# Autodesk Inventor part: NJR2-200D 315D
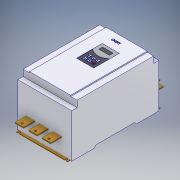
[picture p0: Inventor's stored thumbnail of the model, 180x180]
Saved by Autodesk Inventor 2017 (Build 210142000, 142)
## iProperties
Part Number: NJR2-200D 315D
Material: Типовые
Document SubType Name: Modeling
Designer: RSagdiev
Density: 1 g/cm^3
Appearance: По умолчанию
Author: RSagdiev
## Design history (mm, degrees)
sketch "Эскиз1"
  geometry: L1 (0, 0)-(15.898, 0) reference; L2 (0, 0)-(0, 16.101) reference; L3 (0, 0)-(105, 0); L4 (410, 0)-(410, 206); L5 (410, 241)-(0, 241); L6 (0, 241)-(0, 206); L7 (115, -10)-(295, -10); L8 (295, -10)-(295, 0); L9 (295, 10)-(115, 10); L10 (115, 10)-(115, 10); L11 (115, -10)-(295, 10); L12 (295, -10)-(115, 10); L13 (305, 0)-(410, 0); L14 (115, 0)-(205, 0); L15 (205, 0)-(295, 0); L16 (295, 10)-(295, 10); L17 (115, 0)-(115, -10); L18 (295, 10)-(305, 0); L19 (115, 10)-(105, 0); L20 (410, 241)-(385, 241); L21 (385, 241)-(385, 206); L22 (385, 206)-(410, 206); L23 (410, 206)-(410, 241); L24 (0, 241)-(25, 241); L25 (25, 241)-(25, 206); L26 (25, 206)-(0, 206); L27 (0, 206)-(0, 241); L28 (410, 206)-(410, 241); L29 (0, 206)-(0, 0); 1 further point
  constraints: 58 end point, 17 parallel, 12 perpendicular, 9 horizontal, 4 midpoint, 4 point on line, 2 vertical, 1 other
  dimensions: "d0" = 410 distance of L5.end L5.start; "d1" = 241 distance of L5.start L4.start; "d2" = 180 distance of L9.end L9.start; "d3" = 20 distance of L9.start L7.end; "d4" = 205 distance from line of L14.end L4 (= 0.5 x d0); "d5" = 10 distance of L16.start L8.end; "d6" = 10 distance of L13.start L8.end (= d5); "d7" = 10 distance of L10.end L14.start (= d5); "d8" = 10 distance of L3.end L14.start (= d7); "d9" = 25 distance of L4.end L21.end; "d10" = 35 distance of L21.end L20.end; "d11" = 25 distance of L25.end L6.end; "d12" = 35 distance of L24.end L25.end
extrude "Выдавливание1" new body sketch "Эскиз1" stored distance "d13" = 253; taper "d14" = 0 deg
sketch "Эскиз2"
  geometry: L1 (0, 0)-(253, 0) reference; L2 (253, 360)-(253, 0) reference; L3 (253, 360)-(0, 360) reference; L4 (0, 0)-(0, 360) reference; L5 (0, 0)-(0, 360) reference; L6 (0, 0)-(253, 0) reference; L7 (0, 360)-(30, 360); L8 (30, 360)-(30, 0); L9 (30, 0)-(0, 0); L10 (0, 0)-(0, 360); L11 (253, 360)-(223, 360); L12 (223, 360)-(223, 0); L13 (223, 0)-(253, 0); L14 (253, 0)-(253, 360); 1 further point
  constraints: 16 end point, 4 parallel, 2 horizontal, 2 perpendicular, 2 point on line
  dimensions: "d15" = 30 distance of L8.end L9.end; "d16" = 30 distance of L13.end L12.end
extrude "Выдавливание2" cut sketch "Эскиз2" distance "d17" = 5; taper "d18" = 0 deg
sketch "Эскиз3"
  geometry: L1 (385, 236)-(25, 236) reference; L2 (25, 236)-(25, 206) reference; L3 (25, 206)-(0, 206) reference; L4 (0, 206)-(0, 0) reference; L5 (0, 0)-(105, 0) reference; L6 (105, 0)-(115, 10) reference; L7 (115, 10)-(295, 10) reference; L8 (295, 10)-(305, 0) reference; L9 (305, 0)-(410, 0) reference; L10 (410, 0)-(410, 206) reference; L11 (410, 206)-(385, 206) reference; L12 (385, 206)-(385, 236) reference; L13 (423, 3.5)-(315, 3.5); L14 (315, 3.5)-(315, 0.5); L15 (315, 0.5)-(423, 0.5); L16 (423, 0.5)-(423, 3.5); L17 (115, 10)-(295, 10) reference; L18 (205, 10)-(205, 236); L19 (115, 10)-(105, 0); L20 (95, 3.5)-(95, 0.5); L21 (105, 0)-(0, 0); L22 (-13, 3.5)-(95, 3.5); L23 (-13, 0.5)-(-13, 3.5); L24 (95, 0.5)-(-13, 0.5); 1 further point
  constraints: 22 end point, 4 symmetric about line, 2 midpoint, 2 parallel, 1 horizontal, 1 perpendicular
  dimensions: "d20" = 3 distance of L14.end L13.end; "d21" = 0.5 distance between parallel lines of L9 L15; "d23" = 10 distance from line of L8.end L14; "d24" = 436 distance between parallel lines of L23 L16
extrude "Выдавливание3" new body sketch "Эскиз3" stored distance "d25" = 240; taper "d26" = 0 deg
sketch "Эскиз4"
  geometry: L1 (240, 0)-(0, 0) reference; L2 (0, -108)-(0, 0) reference; L3 (240, -108)-(0, -108) reference; L4 (240, 0)-(240, -108) reference; L5 (240, 0)-(0, 0) reference; L6 (120, 0)-(120, -108); L7 (240, -108)-(0, -108) reference; L8 (240, -328)-(0, -328) reference; L9 (0, -436)-(0, -328) reference; L10 (240, -436)-(0, -436) reference; L11 (240, -328)-(240, -436) reference; L12 (10, -429.5)-(10, -436); L13 (6.5, -429.5)-(6.5, -436); L14 (13.5, -436)-(13.5, -429.5); L15 (230, -429.5)-(230, -436); L16 (226.5, -429.5)-(226.5, -436); L17 (233.5, -436)-(233.5, -429.5); C1 r 3.5 at (10, -6.5); C2 r 3.5 at (230, -6.5); A1 r 3.5 centre (10, -429.5) between (13.5, -429.5) and (6.5, -429.5); A2 r 3.5 centre (10, -436) between (6.5, -436) and (13.5, -436); A3 r 3.5 centre (230, -429.5) between (233.5, -429.5) and (226.5, -429.5); A4 r 3.5 centre (230, -436) between (226.5, -436) and (233.5, -436); 3 further points
  constraints: 18 end point, 8 point on circle, 8 tangent, 6 centre point, 4 midpoint, 2 parallel, 2 perpendicular, 2 point on line
  dimensions: "d27" = 7 diameter of C1; "d28" = 7 diameter of C2 (= d27); "d29" = 220 distance of C2.centre C1.centre; "d31" = 110 distance from line of C1.centre L6 (= 0.5 x d29); "d32" = 110 distance from line of L6 C2.centre (= d31); "d33" = 6.5 distance from line of L1 C1.centre (computed from d27); "d34" = 6.5 distance from line of L1 C2.centre (derived); "d35" = 7 diameter of A2 (= d27); "d36" = 6.5 distance from line of L10 L12.start (computed from d35); "d37" = 7 diameter of A4 (= d35); "d38" = 6.5 distance from line of L10 L15.start (= d36); "d39" = 220 distance of L15.start L12.start (= d29); "d40" = 110 horizontal distance of point (120, -423) L12.start (= d31); "d41" = 110 horizontal distance of point (120, -423) L15.start (derived)
extrude "Выдавливание4" cut sketch "Эскиз4" stored distance "d42" = 240; taper "d43" = 0 deg
node "РабПлоскость1"
sketch "Эскиз5" dims "d56" = 10, "d67" = 10
  geometry: L1 (33.5, 147)-(73.5, 147); L2 (73.5, 147)-(73.5, -367); L3 (73.5, -367)-(33.5, -367); L4 (33.5, -367)-(33.5, 147); L5 (-6.5, 95)-(246.5, 95) reference; L6 (-6.5, -20)-(-6.5, -200) reference; L7 (-6.5, -110)-(246.5, -110); L8 (246.5, -200)-(246.5, -20) reference; L9 (96.75, 147)-(136.75, 147); L10 (136.75, 147)-(136.75, -367); L11 (136.75, -367)-(96.75, -367); L12 (96.75, -367)-(96.75, 147); L13 (160, 147)-(200, 147); L14 (200, 147)-(200, -367); L15 (200, -367)-(160, -367); L16 (160, -367)-(160, 147); C1 r 5 at (53.5, 135); C2 r 5 at (116.75, 135); C3 r 5 at (180, 135); C4 r 5 at (116.75, -355); C5 r 5 at (180, -355); C6 r 5 at (53.5, -355); 1 further point
  constraints: 26 end point, 6 centre point, 3 horizontal, 3 symmetric about line, 2 midpoint, 2 parallel, 1 perpendicular, 23 other
  dimensions: "d45" = 514 distance between parallel lines of L3 L1; "d46" = 40 distance between parallel lines of L2 L4; "d48" = 257 distance between parallel lines of L1 L7 (= 0.5 x d45); "d49" = 40 distance between parallel lines of L4 L6; "d50" = 253 distance between parallel lines of L8 L6 (derived); "d53" = 63.25 distance of L1.start L9.start (= 0.25 x d50); "d59" = 10 diameter of C1; "d60" = 20 distance from line of C1.centre L4; "d61" = 12 distance from line of C1.centre L1; "d64" = 63.25 distance of C1.centre C2.centre (= d53)
extrude "Выдавливание5" new body sketch "Эскиз5" distance "d69" = 5; taper "d70" = 0 deg
node "РабПлоскость2"
sketch "Эскиз6" dims "d79" = 10, "d89" = 10
  geometry: L1 (73.5, 147)-(33.5, 147) reference; L2 (33.5, 147)-(33.5, -367) reference; L3 (33.5, -367)-(73.5, -367) reference; L4 (73.5, -367)-(73.5, 147) reference; L5 (136.75, 147)-(96.75, 147) reference; L6 (96.75, 147)-(96.75, -367) reference; L7 (96.75, -367)-(136.75, -367) reference; L8 (136.75, -367)-(136.75, 147) reference; L9 (200, 147)-(160, 147) reference; L10 (160, 147)-(160, -367) reference; L11 (160, -367)-(200, -367) reference; L12 (200, -367)-(200, 147) reference; L13 (-6.5, -110)-(246.5, -110) reference; L14 (-6.5, -10)-(246.5, -10) reference; L15 (33.5, -10)-(73.5, -10); L16 (73.5, -10)-(73.5, 162); L17 (73.5, 162)-(33.5, 162); L18 (33.5, 162)-(33.5, -10); L19 (96.75, -10)-(136.75, -10); L20 (136.75, -10)-(136.75, 162); L21 (96.75, 162)-(96.75, -10); L22 (136.75, 162)-(96.75, 162); L23 (160, -10)-(200, -10); L24 (200, -10)-(200, 162); L25 (160, 162)-(160, -10); L26 (200, 162)-(160, 162); C1 r 5 at (53.5, -355) reference; C2 r 5 at (53.5, 135) reference; C3 r 5 at (116.75, -355) reference; C4 r 5 at (116.75, 135) reference; C5 r 5 at (180, -355) reference; C6 r 5 at (180, 135) reference; C7 r 5 at (53.5, 150); C8 r 5 at (116.75, 150); C9 r 5 at (180, 150); 8 further points
  constraints: 24 end point, 3 centre point, 3 horizontal, 2 parallel, 2 point on line, 1 collinear, 1 perpendicular, 27 other
  dimensions: "d72" = 40 distance between parallel lines of L16 L18 (= d46); "d73" = 15 distance between parallel lines of L17 L1; "d76" = 63.25 distance of L1.start point (136.75, 147) (= d53); "d81" = 10 diameter of C7; "d82" = 12 distance from line of L17 C7.centre (= d61); "d83" = 20 distance from line of L18 C7.centre (= d60); "d86" = 63.25 distance of C7.centre C8.centre (= d53)
extrude "Выдавливание6" new body sketch "Эскиз6" distance "d91" = 5; taper "d92" = 0 deg
sketch "Эскиз7"
  geometry: L1 (193, -360)-(193, 0) reference; L2 (193, 0)-(0, 0) reference; L3 (0, 0)-(0, -360) reference; L4 (0, -360)-(193, -360) reference; L5 (136.5, -195)-(56.5, -195); L6 (56.5, -195)-(56.5, -119.989); L7 (56.5, -75)-(136.5, -75); L8 (136.5, -75)-(136.5, -119.721); L9 (136.5, -195)-(56.5, -75); L10 (56.5, -195)-(136.5, -75); L11 (136.7, -74.8)-(56.3, -74.8); L12 (56.3, -74.8)-(56.3, -195.2); L13 (56.3, -195.2)-(136.7, -195.2); L14 (136.7, -195.2)-(136.7, -74.8); L15 (136.5, -119.721)-(136.5, -119.989); L16 (136.5, -119.989)-(136.5, -195); L17 (56.5, -119.721)-(56.5, -75); L18 (56.5, -119.989)-(56.5, -119.721); L19 (72.5, -88.361)-(120.5, -88.361); L20 (121.5, -89.361)-(121.5, -105.361); L21 (120.5, -106.361)-(72.5, -106.361); L22 (71.5, -105.361)-(71.5, -89.361); L23 (71.5, -88.361)-(121.5, -106.361); L24 (121.5, -88.361)-(71.5, -106.361); L25 (96.5, -135)-(96.5, -195.2); L26 (76.5, -131.781)-(76.5, -195); L27 (116.5, -131.781)-(116.5, -195); L28 (56.5, -175)-(136.5, -175); L29 (56.5, -155)-(136.5, -155); L30 (70.5, -149)-(82.5, -149); L31 (82.5, -149)-(82.5, -161); L32 (82.5, -161)-(70.5, -161); L33 (70.5, -161)-(70.5, -149); L34 (70.5, -149)-(82.5, -161); L35 (82.5, -149)-(70.5, -161); L36 (70.5, -169)-(82.5, -169); L37 (82.5, -169)-(82.5, -181); L38 (82.5, -181)-(70.5, -181); L39 (70.5, -181)-(70.5, -169); L40 (70.5, -169)-(82.5, -181); L41 (82.5, -169)-(70.5, -181); L42 (110.5, -149)-(122.5, -149); L43 (122.5, -149)-(122.5, -161); L44 (122.5, -161)-(110.5, -161); L45 (110.5, -161)-(110.5, -149); L46 (110.5, -149)-(122.5, -161); L47 (122.5, -149)-(110.5, -161); L48 (110.5, -169)-(122.5, -169); L49 (122.5, -169)-(122.5, -181); L50 (122.5, -181)-(110.5, -181); L51 (110.5, -181)-(110.5, -169); L52 (110.5, -169)-(122.5, -181); L53 (122.5, -169)-(110.5, -181); L54 (90.5, -149)-(102.5, -149); L55 (102.5, -149)-(102.5, -161); L56 (102.5, -161)-(90.5, -161); L57 (90.5, -161)-(90.5, -149); L58 (90.5, -149)-(102.5, -161); L59 (102.5, -149)-(90.5, -161); L60 (90.5, -169)-(102.5, -169); L61 (102.5, -169)-(102.5, -181); L62 (102.5, -181)-(90.5, -181); L63 (90.5, -181)-(90.5, -169); L64 (90.5, -169)-(102.5, -181)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; A1 r 60 centre (96.5, -75) between (56.5, -119.721) and (136.5, -119.721); A2 r 60.2 centre (96.5, -75) between (56.5, -119.989) and (136.5, -119.989); A3 r 1 centre (72.5, -89.361) between (72.5, -88.361) and (71.5, -89.361); A4 r 1 centre (72.5, -105.361) between (71.5, -105.361) and (72.5, -106.361); A5 r 1 centre (120.5, -105.361) between (120.5, -106.361) and (121.5, -105.361); A6 r 1 centre (120.5, -89.361) between (121.5, -89.361) and (120.5, -88.361); 8 further points
  constraints: 122 end point, 26 parallel, 23 point on line, 20 midpoint, 14 point on circle, 13 perpendicular, 8 horizontal, 8 tangent, 6 centre point, 3 equal radius, 1 vertical
  dimensions: "d93" = 80 distance of L7.start L7.end; "d94" = 120 distance of L5.end L7.start; "d95" = 75 distance between parallel lines of L2 L7; "d96" = 56.5 distance between parallel lines of L3 L6; "d97" = 0.2 distance between parallel lines of L7 L11; "d98" = 60 radius of A1; "d99" = 0.2 radial gap between concentric circles of A1 A2; "d100" = 0.2 distance between parallel lines of L6 L12; "d101" = 0.2 distance between parallel lines of L16 L14; "d102" = 0.2 distance between parallel lines of L5 L13; "d103" = 50 distance of L23.end L24.end; "d104" = 18 distance of L24.start L23.end; "d105" = 1 radius of A3; "d106" = 13.36068 distance between parallel lines of L7 L19; "d107" = 15 distance between parallel lines of L17 L22; "d108" = 20 distance between parallel lines of L25 L26 (= 0.25 x d93); "d109" = 20 horizontal distance of L25.end L27.end (= d108); "d110" = 20 distance between parallel lines of L5 L28 (= d108); "d111" = 20 distance between parallel lines of L28 L29 (= d108); "d112" = 12 distance of L31.end L32.end; "d113" = 12 distance of L30.end L31.end; "d114" = 12 distance of L37.end L38.end; "d115" = 12 distance of L36.end L37.end; "d116" = 12 distance of L43.end L44.end; "d117" = 12 distance of L42.end L43.end; "d118" = 12 distance of L49.end L50.end; "d119" = 12 distance of L48.end L49.end; "d120" = 12 distance of L55.end L56.end; "d121" = 12 distance of L54.end L55.end; "d122" = 12 distance of L61.end L62.end; "d123" = 12 distance of L60.end L61.end
  node "Спроецированная петля8"
extrude "Выдавливание7" cut sketch "Эскиз7" distance "d124" = 10; taper "d125" = 0 deg
extrude "Выдавливание8" cut sketch "Эскиз7" distance "d126" = 1; taper "d127" = 0 deg
extrude "Выдавливание9" cut sketch "Эскиз7" distance "d128" = 0.1; taper "d129" = 0 deg
sketch "Эскиз8" dims "d139" = 7, "d140" = 7
  geometry: L1 (0, 12)-(0, 0) reference; L2 (1, 4)-(10.784, 4); L3 (0, 0)-(12, 0) reference; L4 (43, 4)-(49.667, 4); L5 (3, -16)-(9.899, -16); L6 (42, -16)-(49.667, -16); L7 (0, -8)-(0, -20) reference; L8 (40, 12)-(40, 0) reference; L9 (40, -8)-(40, -20) reference; L10 (40, 0)-(52, 0) reference; L11 (40, -20)-(52, -20) reference; L12 (0, -20)-(12, -20) reference; L13 (20, 12)-(20, 0) reference; L14 (20, 0)-(32, 0) reference; L15 (32, 0)-(32, 12) reference; L16 (32, 12)-(20, 12) reference; L17 (20, -8)-(20, -20) reference; L18 (20, -20)-(32, -20) reference; L19 (32, -20)-(32, -8) reference; L20 (32, -8)-(20, -8) reference; L21 (20, 12)-(32, 0); L22 (32, 0)-(32, 12) reference; L23 (32, 12)-(20, 0); L24 (32, -8)-(20, -8) reference; L25 (20, -8)-(32, -20); L26 (32, -8)-(20, -20); L27 (26, 9.5)-(29.031, 4.25); L28 (29.031, 4.25)-(22.969, 4.25); L29 (22.969, 4.25)-(26, 9.5); L30 (26, -17.5)-(22.969, -12.25); L31 (22.969, -12.25)-(29.031, -12.25); L32 (29.031, -12.25)-(26, -17.5); 5 further points
  constraints: 28 end point, 8 horizontal, 2 coincident, 2 midpoint, 2 perpendicular, 2 vertical alignment, 18 other
  dimensions: "d130" = 1 distance from line of L1 L2.start; "d131" = 4 distance between parallel lines of L3 L2; "d133" = 3 distance from line of L7 L5.start; "d134" = 3 distance from line of L8 L4.start; "d135" = 2 distance from line of L9 L6.start; "d136" = 4 distance between parallel lines of L10 L4 (= d131); "d137" = 4 distance between parallel lines of L11 L6 (= d131); "d138" = 4 distance between parallel lines of L12 L5 (= d131)
  node "Спроецированная петля9"
  node "Спроецированная петля10"
feature "Рельеф1" dims "d141" = 0.1, "d142" = 0
feature "Рельеф2" dims "d143" = 0.1, "d144" = 0
feature "Рельеф3" dims "d145" = 0.1, "d146" = 0
feature "Рельеф4" dims "d147" = 0.1, "d148" = 0
feature "Рельеф5" dims "d149" = 0.1, "d150" = 0
feature "Рельеф6" dims "d151" = 0.1, "d152" = 0
sketch "Эскиз9"
  geometry: L1 (61.3, -40)-(127.615, -40); L2 (56.3, -195.2)-(56.3, -74.8) reference; L3 (-30, 0)-(223, 0) reference; 1 further point
  constraints: 2 end point, 2 horizontal
  dimensions: "d153" = 5 distance from line of L2 L1.start; "d154" = 40 distance between parallel lines of L3 L1
feature "Рельеф7" sketch "Эскиз9" dims "d155" = 0.1, "d156" = 0
node "Твердое тело1"
node "Спроецированная петля1"
node "Спроецированная петля2"
node "Твердое тело2"
node "Спроецированная петля3"
node "Спроецированная петля4"
node "Твердое тело3"
node "Спроецированная петля5"
node "Спроецированная петля6"
node "Спроецированная петля7"
node "Твердое тело4"
other parameters: "d71" = -35
